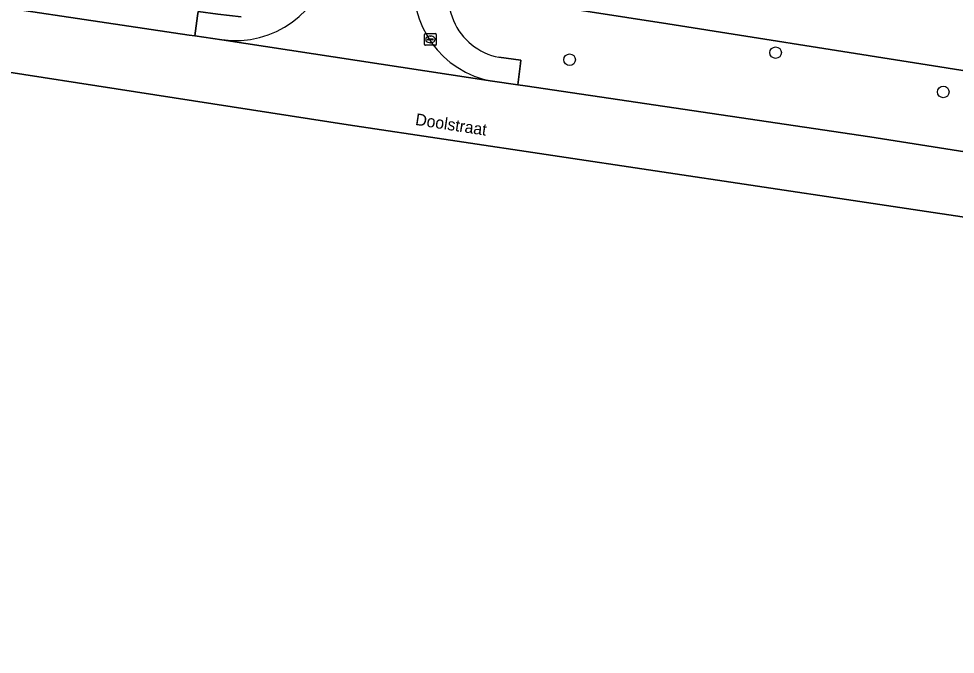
# Model space of a CAD drawing. Extents: x 164148 to 165261, y 382513 to 383432.
# Drawn here: x 164429 to 164508.4, y 382807.8 to 382861.7 of the extents above; entities that cross this region are included whole.
import ezdxf

# ---------------------------------------------------------------- set-up
doc = ezdxf.new("R2010")
doc.units = 0
for name, color, linetype in [('IMGEO_Boom', 7, 'Continuous'), ('IMGEO_Greppel_droge_sloot', 7, 'Continuous'), ('IMGEO_Groenvoorziening', 7, 'Continuous'), ('IMGEO_Openbare_ruimte_label', 7, 'Continuous'), ('IMGEO_Rijbaan_lokaal_gesloten', 7, 'Continuous'), ('IMGEO_Rijbaan_lokaal_open', 7, 'Continuous'), ('IMGEO_Rioolput', 7, 'Continuous'), ('IMGEO_Voetpad_open', 7, 'Continuous')]:
    doc.layers.add(name, color=color, linetype=linetype)

msp = doc.modelspace()

# ---------------------------------------------------------------- linework, layer by layer
at = {"layer": 'IMGEO_Boom'}
for centre in [(164493.202, 382858.796), (164475.726, 382858.194), (164507.427, 382855.463)]:
    msp.add_circle(centre, 0.489, dxfattribs=at)
at = {"layer": 'IMGEO_Greppel_droge_sloot'}
msp.add_lwpolyline([(164527.808, 382867.71), (164528.242, 382867.643), (164528.255, 382867.732), (164527.513, 382867.841), (164483.733, 382874.094), (164468.94, 382876.903), (164467.772, 382876.998), (164467.128, 382872.489), (164466.901, 382870.898), (164466.447, 382867.72), (164465.924, 382864.054), (164484.051, 382861.245), (164524.835, 382854.782), (164525.957, 382854.773), (164526.609, 382859.328), (164526.913, 382861.453), (164527.19, 382863.393)], close=True, dxfattribs=at)
at = {"layer": 'IMGEO_Groenvoorziening'}
for points in [[(164394.559, 382869.76), (164395.998, 382869.539), (164395.677, 382867.443), (164396.404, 382867.334), (164443.459, 382860.284), (164443.914, 382860.221), (164444.167, 382861.929), (164444.22, 382862.289), (164445.867, 382862.058), (164447.854, 382861.836)], [(164526.374, 382854.707), (164525.957, 382854.773), (164524.835, 382854.782), (164484.051, 382861.245), (164465.924, 382864.054)], [(164604.586, 382830.457), (164582.41, 382833.88), (164500.334, 382846.167), (164456.924, 382852.665), (164408.057, 382860.247), (164402.983, 382860.898), (164397.573, 382827.291), (164390.779, 382784.365), (164387.209, 382761.399), (164383.845, 382738.669), (164378.996, 382706.807)], [(164469.716, 382858.402), (164471.598, 382858.146), (164471.565, 382857.886), (164471.335, 382856.066), (164471.939, 382855.982), (164501.188, 382851.646), (164520.361, 382848.623), (164521.046, 382848.53), (164521.333, 382850.492), (164521.357, 382850.657), (164521.649, 382850.615)]]:
    msp.add_lwpolyline(points, dxfattribs=at)
for centre, radius, start, end in [((164470.735, 382863.571), 5.282, 174.14547, 202.93548), ((164470.719, 382863.573), 5.268, 203.02506, 259.02211)]:
    msp.add_arc(centre, radius, start, end, dxfattribs=at)
at = {"layer": 'IMGEO_Rijbaan_lokaal_gesloten'}
for points in [[(164601.872, 382836.441), (164580.335, 382839.876), (164577.371, 382840.307), (164541.34, 382845.725), (164540.462, 382845.846), (164539.367, 382845.996), (164539.338, 382846), (164539.309, 382846.004), (164522.349, 382848.352), (164521.046, 382848.53), (164520.361, 382848.623), (164501.188, 382851.646), (164471.939, 382855.982), (164471.335, 382856.066), (164469.168, 382856.367), (164446.231, 382859.897), (164443.914, 382860.221), (164443.459, 382860.284), (164396.404, 382867.334), (164395.677, 382867.443), (164393.451, 382867.778)], [(164380.862, 382863.974), (164394.925, 382861.905), (164395.466, 382861.842), (164395.789, 382861.801), (164402.983, 382860.898), (164408.057, 382860.247), (164456.924, 382852.665), (164500.334, 382846.167), (164582.41, 382833.88), (164604.586, 382830.457)]]:
    msp.add_lwpolyline(points, dxfattribs=at)
at = {"layer": 'IMGEO_Rijbaan_lokaal_open'}
msp.add_lwpolyline([(164446.231, 382859.897), (164469.168, 382856.367)], dxfattribs=at)
for centre, radius, start, end in [((164447.382, 382867.935), 8.12, 261.84817, 350.64704), ((164470.627, 382864.363), 8.128, 171.53911, 259.66233)]:
    msp.add_arc(centre, radius, start, end, dxfattribs=at)
at = {"layer": 'IMGEO_Rioolput'}
for p, q in [((164463.414, 382859.492), (164463.414, 382860.344)), ((164463.489, 382860.418), (164464.341, 382860.418)), ((164463.673, 382859.912), (164463.673, 382859.924)), ((164463.716, 382859.961), (164464.114, 382859.961)), ((164463.902, 382860.198), (164463.927, 382860.198)), ((164464.157, 382859.924), (164464.157, 382859.912)), ((164464.415, 382860.344), (164464.415, 382859.492)), ((164464.341, 382859.418), (164463.489, 382859.418)), ((164464.111, 382859.875), (164463.713, 382859.875)), ((164463.925, 382859.638), (164463.9, 382859.638))]:
    msp.add_line(p, q, dxfattribs=at)
for points in [[(164463.414, 382859.492), (164463.414, 382860.344)], [(164463.489, 382860.418), (164464.341, 382860.418)], [(164464.415, 382860.344), (164464.415, 382859.492)], [(164464.341, 382859.418), (164463.489, 382859.418)]]:
    msp.add_lwpolyline(points, dxfattribs=at)
for centre, radius, start, end in [((164463.491, 382860.342), 0.0765, 91.55205, 178.44795), ((164463.491, 382860.342), 0.0765, 91.55205, 178.44795), ((164463.713, 382859.921), 0.0403, 85.87752, 175.75265), ((164463.71, 382859.911), 0.0366, 178.93798, 274.71019), ((164464.114, 382859.918), 0.043, 264.86636, 352.45326), ((164464.118, 382859.923), 0.0386, 1.73085, 96.63898), ((164464.339, 382860.342), 0.0765, 1.55205, 88.44795), ((164464.339, 382860.342), 0.0765, 1.55205, 88.44795), ((164463.491, 382859.494), 0.0765, 181.55205, 268.44795), ((164463.491, 382859.494), 0.0765, 181.55205, 268.44795), ((164464.339, 382859.494), 0.0765, 271.55205, 358.44795), ((164464.339, 382859.494), 0.0765, 271.55205, 358.44795)]:
    msp.add_arc(centre, radius, start, end, dxfattribs=at)
for centre, major_axis, ratio, start_param, end_param in [((164463.901, 382859.918), (-0.387, 0.002), 0.722429, 4.712389, 7.853982), ((164463.926, 382859.918), (-0.39, 0.002), 0.717154, 1.570796, 4.712389)]:
    msp.add_ellipse(centre, major_axis=major_axis, ratio=ratio, start_param=start_param, end_param=end_param, dxfattribs=at)
at = {"layer": 'IMGEO_Voetpad_open'}
for points in [[(164447.854, 382861.836), (164445.867, 382862.058), (164444.22, 382862.289), (164444.167, 382861.929), (164443.914, 382860.221), (164446.231, 382859.897)], [(164469.168, 382856.367), (164471.335, 382856.066), (164471.565, 382857.886), (164471.598, 382858.146), (164469.716, 382858.402)]]:
    msp.add_lwpolyline(points, dxfattribs=at)
for centre, radius, start, end in [((164447.382, 382867.935), 8.12, 261.84817, 350.64704), ((164470.627, 382864.363), 8.128, 171.53911, 259.66233), ((164470.735, 382863.571), 5.282, 174.14547, 202.93548), ((164470.719, 382863.573), 5.268, 203.02506, 259.02211)]:
    msp.add_arc(centre, radius, start, end, dxfattribs=at)

# ---------------------------------------------------------------- texts
at = {"layer": 'IMGEO_Openbare_ruimte_label'}
msp.add_text('Doolstraat', height=1, rotation=351.31915, dxfattribs=at).set_placement((164462.585, 382852.669))

doc.saveas('drawing.dxf')
